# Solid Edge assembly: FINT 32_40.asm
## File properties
Title: Zylinder
Author: bmolnar
Template: iso assembly.asm
Last saved by: bmolnar
Revision: 13
Application: Solid Edge
Username: bmolnar
Dokumentum tartalom típus: 1
Document Number: FINT 32/40
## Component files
hrungsstange.par
Profilrohr.par
Platte.par
Kolbenstange.par
Kit_1.par
Kit_2.par
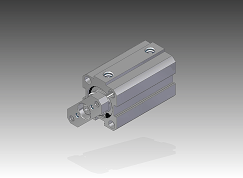
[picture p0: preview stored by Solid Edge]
